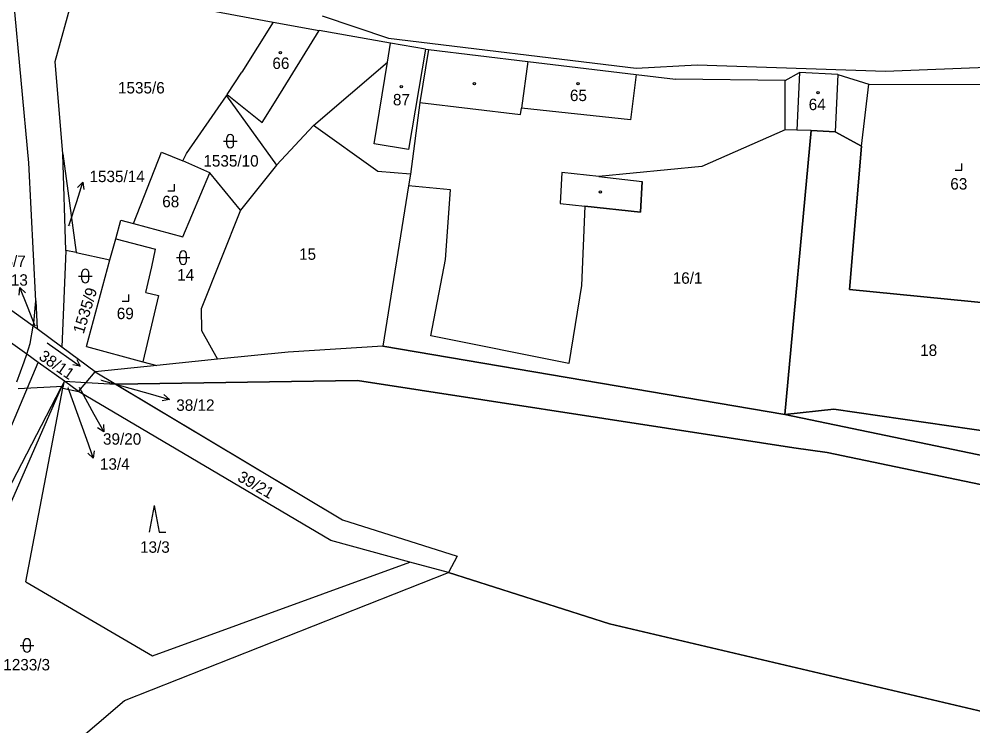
# Model space of a CAD drawing. Extents: x -801826 to -800592, y -1032871 to -1031813.
# Drawn here: x -801600 to -801458.2, y -1032403.9 to -1032298.8 of the extents above; entities that cross this region are included whole.
import ezdxf

# ---------------------------------------------------------------- set-up
doc = ezdxf.new("R2010")
doc.units = 0
for name, color, linetype in [('Vrstva 1', 7, 'Continuous'), ('Vrstva 16', 7, 'Continuous'), ('Vrstva 18', 7, 'Continuous'), ('Vrstva 19', 7, 'Continuous'), ('Vrstva 25', 7, 'Continuous'), ('Vrstva 4', 7, 'Continuous')]:
    doc.layers.add(name, color=color, linetype=linetype)

msp = doc.modelspace()

# ---------------------------------------------------------------- linework, layer by layer
at = {"layer": 'Vrstva 1'}
for p, q in [((-801598.56, -1032320.14), (-801601.16, -1032291.94)), ((-801594.62, -1032305.08), (-801591.53, -1032293.73)), ((-801591.53, -1032293.73), (-801562.22, -1032299.23)), ((-801562.22, -1032299.23), (-801566.87, -1032306.67)), ((-801562.22, -1032299.23), (-801555.36, -1032300.46)), ((-801554.92, -1032298.29), (-801545.05, -1032301.61)), ((-801544.78, -1032302.35), (-801555.36, -1032300.46)), ((-801545.05, -1032301.61), (-801508.22, -1032306.08)), ((-801545.24, -1032305.18), (-801544.78, -1032302.35)), ((-801539.59, -1032303.23), (-801544.78, -1032302.35)), ((-801539.1, -1032303.29), (-801540.41, -1032311.15)), ((-801539.59, -1032303.23), (-801539.1, -1032303.29)), ((-801539.1, -1032303.29), (-801524.35, -1032305.05)), ((-801593.48, -1032318.83), (-801594.62, -1032305.08)), ((-801524.35, -1032305.05), (-801508.26, -1032307.02)), ((-801471.17, -1032306.51), (-801432.98, -1032305)), ((-801556.23, -1032314.62), (-801545.24, -1032305.18)), ((-801508.22, -1032306.08), (-801499.17, -1032305.58)), ((-801499.17, -1032305.58), (-801471.17, -1032306.51)), ((-801569.05, -1032310), (-801566.87, -1032306.67)), ((-801508.26, -1032307.02), (-801502.41, -1032307.7)), ((-801486.1, -1032307.89), (-801502.41, -1032307.7)), ((-801486.1, -1032307.89), (-801483.95, -1032306.72)), ((-801486.06, -1032315.22), (-801486.1, -1032307.89)), ((-801478.24, -1032306.99), (-801483.95, -1032306.72)), ((-801478.24, -1032306.99), (-801473.65, -1032308.44)), ((-801474.72, -1032317.65), (-801473.65, -1032308.44)), ((-801473.65, -1032308.44), (-801445.24, -1032308.56)), ((-801575.11, -1032318.77), (-801569.18, -1032310.2)), ((-801569.18, -1032310.2), (-801569.05, -1032310)), ((-801569.18, -1032310.2), (-801561.73, -1032320.51)), ((-801540.41, -1032311.15), (-801541.79, -1032321.83)), ((-801561.73, -1032320.51), (-801556.23, -1032314.62)), ((-801546.68, -1032321.42), (-801556.23, -1032314.62)), ((-801486.06, -1032315.22), (-801498.49, -1032320.71)), ((-801486.06, -1032315.22), (-801498.49, -1032320.71)), ((-801486.13, -1032357.6), (-801482.22, -1032315.36)), ((-801486.13, -1032357.6), (-801482.22, -1032315.36)), ((-801482.22, -1032315.36), (-801486.13, -1032357.6)), ((-801484.35, -1032315.28), (-801486.06, -1032315.22)), ((-801484.35, -1032315.28), (-801486.06, -1032315.22)), ((-801482.22, -1032315.36), (-801484.35, -1032315.28)), ((-801482.22, -1032315.36), (-801484.35, -1032315.28)), ((-801482.22, -1032315.36), (-801478.64, -1032315.52)), ((-801478.64, -1032315.52), (-801482.22, -1032315.36)), ((-801478.64, -1032315.52), (-801474.72, -1032317.65)), ((-801474.72, -1032317.65), (-801478.64, -1032315.52)), ((-801474.72, -1032317.65), (-801476.52, -1032339)), ((-801476.52, -1032339), (-801474.72, -1032317.65)), ((-801593.48, -1032318.83), (-801591.53, -1032333.51)), ((-801593.07, -1032333.18), (-801593.48, -1032318.83)), ((-801583, -1032329.19), (-801578.81, -1032318.58)), ((-801578.81, -1032318.58), (-801575.67, -1032319.86)), ((-801575.67, -1032319.86), (-801575.11, -1032318.77)), ((-801597.54, -1032340.67), (-801598.56, -1032320.14)), ((-801571.66, -1032321.66), (-801575.67, -1032319.86)), ((-801561.73, -1032320.51), (-801567.09, -1032327.19)), ((-801498.49, -1032320.71), (-801513.81, -1032322.2)), ((-801498.49, -1032320.71), (-801513.81, -1032322.2)), ((-801575.67, -1032331.16), (-801571.66, -1032321.66)), ((-801567.09, -1032327.19), (-801571.66, -1032321.66)), ((-801541.79, -1032321.83), (-801546.68, -1032321.42)), ((-801541.79, -1032321.83), (-801542.1, -1032323.55)), ((-801542.1, -1032323.55), (-801545.93, -1032347.42)), ((-801542.1, -1032323.55), (-801545.93, -1032347.42)), ((-801535.87, -1032324.16), (-801542.1, -1032323.55)), ((-801535.87, -1032324.16), (-801542.1, -1032323.55)), ((-801513.81, -1032322.2), (-801507.36, -1032322.91)), ((-801513.81, -1032322.2), (-801507.36, -1032322.91)), ((-801507.6, -1032327.5), (-801507.36, -1032322.91)), ((-801507.36, -1032322.91), (-801507.6, -1032327.5)), ((-801536.58, -1032334.55), (-801535.87, -1032324.16)), ((-801536.58, -1032334.55), (-801535.87, -1032324.16)), ((-801567.09, -1032327.19), (-801572.94, -1032341.86)), ((-801515.85, -1032326.59), (-801516.35, -1032338.41)), ((-801515.85, -1032326.59), (-801516.35, -1032338.41)), ((-801515.85, -1032326.59), (-801507.6, -1032327.5)), ((-801507.6, -1032327.5), (-801515.85, -1032326.59)), ((-801585.64, -1032331.44), (-801584.9, -1032328.68)), ((-801584.9, -1032328.68), (-801583, -1032329.19)), ((-801583, -1032329.19), (-801575.67, -1032331.16)), ((-801597.9, -1032344.43), (-801616.83, -1032331.02)), ((-801586.49, -1032334.59), (-801585.64, -1032331.44)), ((-801585.64, -1032331.44), (-801579.7, -1032333.01)), ((-801598.87, -1032348.64), (-801621.74, -1032332.23)), ((-801593.07, -1032333.18), (-801593.66, -1032347.57)), ((-801591.53, -1032333.51), (-801593.07, -1032333.18)), ((-801591.53, -1032333.51), (-801586.49, -1032334.59)), ((-801580.27, -1032335.61), (-801579.7, -1032333.01)), ((-801589.96, -1032347.5), (-801586.49, -1032334.59)), ((-801538.75, -1032345.88), (-801536.58, -1032334.55)), ((-801538.75, -1032345.88), (-801536.58, -1032334.55)), ((-801581.17, -1032339.43), (-801580.27, -1032335.61)), ((-801516.35, -1032338.41), (-801518.25, -1032349.99)), ((-801516.35, -1032338.41), (-801518.25, -1032349.99)), ((-801476.52, -1032339), (-801449.11, -1032341.7)), ((-801449.11, -1032341.7), (-801476.52, -1032339)), ((-801579.27, -1032339.88), (-801581.6, -1032349.75)), ((-801581.17, -1032339.43), (-801579.27, -1032339.88)), ((-801597.83, -1032344.02), (-801597.54, -1032340.67)), ((-801597.54, -1032340.67), (-801597.33, -1032344.84)), ((-801572.94, -1032341.86), (-801572.87, -1032345.12)), ((-801598.36, -1032347.05), (-801597.9, -1032344.43)), ((-801597.9, -1032344.43), (-801597.83, -1032344.02)), ((-801597.33, -1032344.84), (-801597.9, -1032344.43)), ((-801593.66, -1032347.57), (-801597.33, -1032344.84)), ((-801572.87, -1032345.12), (-801570.52, -1032349.38)), ((-801518.25, -1032349.99), (-801538.75, -1032345.88)), ((-801518.25, -1032349.99), (-801538.75, -1032345.88)), ((-801598.87, -1032348.64), (-801598.36, -1032347.05)), ((-801588.7, -1032351.25), (-801593.66, -1032347.57)), ((-801589.96, -1032347.5), (-801581.6, -1032349.75)), ((-801545.93, -1032347.42), (-801560.01, -1032348.3)), ((-801545.93, -1032347.42), (-801560.01, -1032348.3)), ((-801545.93, -1032347.42), (-801486.13, -1032357.6)), ((-801545.93, -1032347.42), (-801486.13, -1032357.6)), ((-801486.13, -1032357.6), (-801545.93, -1032347.42)), ((-801599.23, -1032349.77), (-801598.87, -1032348.64)), ((-801597.19, -1032349.85), (-801598.87, -1032348.64)), ((-801560.01, -1032348.3), (-801570.52, -1032349.38)), ((-801560.01, -1032348.3), (-801570.52, -1032349.38)), ((-801613.02, -1032387.52), (-801597.19, -1032349.85)), ((-801600.36, -1032352.73), (-801599.23, -1032349.77)), ((-801593.28, -1032352.64), (-801597.19, -1032349.85)), ((-801579.52, -1032350.31), (-801588.7, -1032351.25)), ((-801579.52, -1032350.31), (-801588.7, -1032351.25)), ((-801581.6, -1032349.75), (-801579.52, -1032350.31)), ((-801570.52, -1032349.38), (-801579.52, -1032350.31)), ((-801570.52, -1032349.38), (-801579.52, -1032350.31)), ((-801590.03, -1032352.83), (-801588.7, -1032351.25)), ((-801588.7, -1032351.25), (-801585.61, -1032353.1)), ((-801588.7, -1032351.25), (-801585.61, -1032353.1)), ((-801593.28, -1032352.64), (-801593.74, -1032353.6)), ((-801593.48, -1032353.66), (-801593.28, -1032352.64)), ((-801591.15, -1032354.17), (-801593.28, -1032352.64)), ((-801593.28, -1032352.64), (-801590.03, -1032352.83)), ((-801591.15, -1032354.17), (-801590.03, -1032352.83)), ((-801590.03, -1032352.83), (-801585.61, -1032353.1)), ((-801585.61, -1032353.1), (-801549.67, -1032352.54)), ((-801585.61, -1032353.1), (-801549.67, -1032352.54)), ((-801549.67, -1032352.54), (-801585.61, -1032353.1)), ((-801585.61, -1032353.1), (-801551.92, -1032373.28)), ((-801494.39, -1032361.07), (-801549.67, -1032352.54)), ((-801549.67, -1032352.54), (-801494.39, -1032361.07)), ((-801494.39, -1032361.07), (-801549.67, -1032352.54)), ((-801593.74, -1032353.6), (-801614.36, -1032400.55)), ((-801604.31, -1032373.94), (-801593.74, -1032353.6)), ((-801599.02, -1032382.48), (-801593.48, -1032353.66)), ((-801593.74, -1032353.6), (-801593.48, -1032353.66)), ((-801593.48, -1032353.66), (-801591.15, -1032354.17)), ((-801553.65, -1032376.35), (-801591.15, -1032354.17)), ((-801478.84, -1032356.78), (-801486.13, -1032357.6)), ((-801486.13, -1032357.6), (-801478.84, -1032356.78)), ((-801478.84, -1032356.78), (-801486.13, -1032357.6)), ((-801486.13, -1032357.6), (-801422.46, -1032370.88)), ((-801422.46, -1032370.88), (-801486.13, -1032357.6)), ((-801486.13, -1032357.6), (-801422.46, -1032370.88)), ((-801445.51, -1032361.66), (-801478.84, -1032356.78)), ((-801478.84, -1032356.78), (-801445.51, -1032361.66)), ((-801445.51, -1032361.66), (-801478.84, -1032356.78)), ((-801484.81, -1032362.56), (-801494.39, -1032361.07)), ((-801494.39, -1032361.07), (-801484.81, -1032362.56)), ((-801484.81, -1032362.56), (-801494.39, -1032361.07)), ((-801479.83, -1032363.24), (-801484.81, -1032362.56)), ((-801484.81, -1032362.56), (-801479.83, -1032363.24)), ((-801479.83, -1032363.24), (-801484.81, -1032362.56)), ((-801423.35, -1032375.12), (-801479.83, -1032363.24)), ((-801479.83, -1032363.24), (-801423.35, -1032375.12)), ((-801423.35, -1032375.12), (-801479.83, -1032363.24)), ((-801551.92, -1032373.28), (-801534.88, -1032378.68)), ((-801551.92, -1032373.28), (-801534.88, -1032378.68)), ((-801541.89, -1032379.56), (-801553.65, -1032376.35)), ((-801534.88, -1032378.68), (-801536.17, -1032381.12)), ((-801534.88, -1032378.68), (-801536.17, -1032381.12)), ((-801580.18, -1032393.5), (-801541.89, -1032379.56)), ((-801536.17, -1032381.12), (-801541.89, -1032379.56)), ((-801584.32, -1032400.15), (-801536.17, -1032381.12)), ((-801512.18, -1032388.72), (-801536.17, -1032381.12)), ((-801536.17, -1032381.12), (-801512.18, -1032388.72)), ((-801599.02, -1032382.48), (-801580.18, -1032393.5)), ((-801448.68, -1032403.68), (-801512.18, -1032388.72)), ((-801512.18, -1032388.72), (-801448.68, -1032403.68)), ((-801597.79, -1032411.61), (-801584.32, -1032400.15))]:
    msp.add_line(p, q, dxfattribs=at)
msp.add_lwpolyline([(-801585.61, -1032353.1), (-801585.58, -1032353.12), (-801551.92, -1032373.28)], dxfattribs=at)
at = {"layer": 'Vrstva 16'}
for p, q in [((-801591.44, -1032325.88), (-801590.54, -1032323.02)), ((-801592.59, -1032329.53), (-801591.44, -1032325.88)), ((-801598.78, -1032341.51), (-801599.88, -1032338.72)), ((-801597.62, -1032344.43), (-801598.78, -1032341.51)), ((-801587.82, -1032352.49), (-801580.52, -1032354.54)), ((-801593.52, -1032353.44), (-801600.14, -1032353.78)), ((-801592.76, -1032353.56), (-801590, -1032361.28)), ((-801591.08, -1032353.55), (-801588.87, -1032357.57)), ((-801580.52, -1032354.54), (-801577.63, -1032355.35)), ((-801588.87, -1032357.57), (-801587.43, -1032360.2)), ((-801590, -1032361.28), (-801588.99, -1032364.11))]:
    msp.add_line(p, q, dxfattribs=at)
for points in [[(-801591.32, -1032323.82), (-801590.54, -1032323.02), (-801590.36, -1032324.12)], [(-801599.98, -1032339.83), (-801599.88, -1032338.72), (-801599.05, -1032339.47)], [(-801578.46, -1032354.6), (-801577.63, -1032355.35), (-801578.73, -1032355.56)], [(-801587.47, -1032359.08), (-801587.43, -1032360.2), (-801588.35, -1032359.56)], [(-801588.86, -1032363), (-801588.99, -1032364.11), (-801589.8, -1032363.33)]]:
    msp.add_lwpolyline(points, dxfattribs=at)
at = {"layer": 'Vrstva 25'}
for p, q in [((-801569.1, -1032317.43), (-801569.1, -1032316.43)), ((-801568.1, -1032317.43), (-801568.1, -1032316.43)), ((-801569.6, -1032316.93), (-801567.6, -1032316.93)), ((-801459.79, -1032321.23), (-801459.79, -1032320.23)), ((-801460.79, -1032321.23), (-801459.79, -1032321.23)), ((-801576.9, -1032324.32), (-801576.9, -1032323.32)), ((-801577.9, -1032324.32), (-801576.9, -1032324.32)), ((-801576.61, -1032334.26), (-801574.61, -1032334.26)), ((-801576.11, -1032334.76), (-801576.11, -1032333.76)), ((-801575.11, -1032334.76), (-801575.11, -1032333.76)), ((-801591.16, -1032336.99), (-801589.16, -1032336.99)), ((-801590.66, -1032337.49), (-801590.66, -1032336.49)), ((-801589.66, -1032337.49), (-801589.66, -1032336.49)), ((-801583.7, -1032340.74), (-801583.7, -1032339.74)), ((-801584.7, -1032340.74), (-801583.7, -1032340.74)), ((-801595.81, -1032346.94), (-801590.91, -1032350.4)), ((-801579.93, -1032371.12), (-801580.67, -1032375.12)), ((-801579.93, -1032371.12), (-801579.2, -1032375.12)), ((-801579.2, -1032375.12), (-801578.2, -1032375.12)), ((-801599.33, -1032392.46), (-801599.33, -1032391.46)), ((-801598.33, -1032392.46), (-801598.33, -1032391.46)), ((-801599.83, -1032391.96), (-801597.83, -1032391.96))]:
    msp.add_line(p, q, dxfattribs=at)
msp.add_lwpolyline([(-801591.44, -1032349.42), (-801590.91, -1032350.4), (-801592.02, -1032350.23)], dxfattribs=at)
for centre in [(-801561.15, -1032303.77), (-801543.17, -1032308.81), (-801532.3, -1032308.35), (-801516.88, -1032308.37), (-801481.19, -1032309.7), (-801513.55, -1032324.47)]:
    msp.add_circle(centre, 0.175, dxfattribs=at)
for centre, start, end in [((-801568.6, -1032316.43), 0, 180), ((-801568.6, -1032317.43), 180, 0), ((-801575.61, -1032333.76), 0, 180), ((-801575.61, -1032334.76), 180, 0), ((-801590.16, -1032336.49), 0, 180), ((-801590.16, -1032337.49), 180, 0), ((-801598.83, -1032391.46), 0, 180), ((-801598.83, -1032392.46), 180, 0)]:
    msp.add_arc(centre, 0.5, start, end, dxfattribs=at)
at = {"layer": 'Vrstva 4'}
for p, q in [((-801561.79, -1032310.84), (-801555.36, -1032300.46)), ((-801539.59, -1032303.23), (-801542.09, -1032318.17)), ((-801524.35, -1032305.05), (-801525.28, -1032312.03)), ((-801547.22, -1032317.34), (-801545.24, -1032305.18)), ((-801508.26, -1032307.02), (-801509.08, -1032313.75)), ((-801483.95, -1032306.72), (-801484.35, -1032315.28)), ((-801478.24, -1032306.99), (-801478.64, -1032315.52)), ((-801569.05, -1032310), (-801563.85, -1032314.16)), ((-801563.85, -1032314.16), (-801561.79, -1032310.84)), ((-801540.41, -1032311.15), (-801525.43, -1032312.97)), ((-801525.43, -1032312.97), (-801525.28, -1032312.03)), ((-801509.08, -1032313.75), (-801525.28, -1032312.03)), ((-801542.09, -1032318.17), (-801547.22, -1032317.34)), ((-801519.29, -1032321.6), (-801519.53, -1032326.19)), ((-801513.81, -1032322.2), (-801519.29, -1032321.6)), ((-801519.53, -1032326.19), (-801515.85, -1032326.59))]:
    msp.add_line(p, q, dxfattribs=at)

# ---------------------------------------------------------------- texts
at = {"layer": 'Vrstva 16'}
for s, p in [('1535/14', (-801589.54, -1032323.02)), ('1535/13', (-801606.92, -1032338.43)), ('38/12', (-801576.63, -1032357.05)), ('39/20', (-801587.53, -1032362.09)), ('13/4', (-801587.99, -1032365.81))]:
    msp.add_text(s, height=1.7, dxfattribs=at).set_placement(p)
at = {"layer": 'Vrstva 18'}
for s, height, p in [('1535/6', 1.7, (-801585.3, -1032309.83)), ('1535/10', 1.7, (-801572.6, -1032320.71)), ('1535/14', 0.1, (-801592.81, -1032329.53)), ('15', 1.7, (-801558.37, -1032334.58)), ('1535/7', 1.7, (-801605.97, -1032335.64)), ('14', 1.7, (-801576.5, -1032337.66)), ('16/1', 1.7, (-801502.8, -1032338.14)), ('1535/13', 0.1, (-801597.85, -1032344.43)), ('18', 1.7, (-801466, -1032348.88)), ('1233/5', 0.1, (-801593.73, -1032353.44)), ('38/12', 0.1, (-801587.99, -1032352.49)), ('13/4', 0.1, (-801592.89, -1032353.56)), ('39/20', 0.1, (-801591.27, -1032353.55)), ('13/3', 1.7, (-801582.02, -1032378.17)), ('1233/3', 1.7, (-801602.36, -1032395.67))]:
    msp.add_text(s, height=height, dxfattribs=at).set_placement(p)
for s, rotation, p in [('1535/9', 72.8455, (-801590.42, -1032345.7)), ('38/11', 325.3156, (-801597.22, -1032349.28)), ('39/21', 329.8382, (-801567.67, -1032367.35))]:
    msp.add_text(s, height=1.7, rotation=rotation, dxfattribs=at).set_placement(p)
at = {"layer": 'Vrstva 19'}
for s, p in [('66', (-801562.34, -1032306.18)), ('65', (-801518.09, -1032310.96)), ('87', (-801544.41, -1032311.6)), ('64', (-801482.58, -1032312.31)), ('63', (-801461.52, -1032324.13)), ('68', (-801578.72, -1032326.76)), ('69', (-801585.48, -1032343.41))]:
    msp.add_text(s, height=1.7, dxfattribs=at).set_placement(p)

doc.saveas('drawing.dxf')
